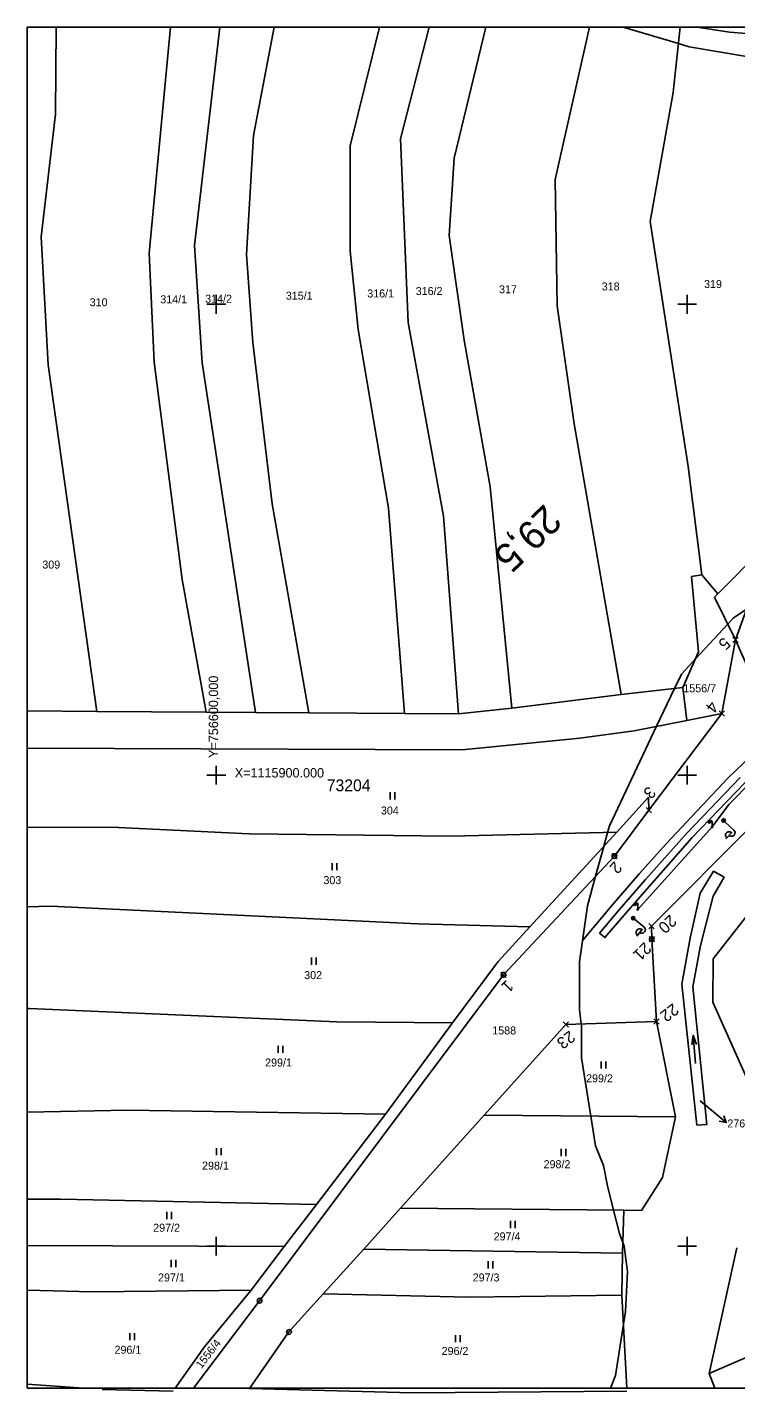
# Model space of a CAD drawing. Extents: x -756640 to -756220, y -1116031 to -1115741.
# Drawn here: x -756640.1 to -756489.7, y -1116031.1 to -1115741.2 of the extents above; entities that cross this region are included whole.
import ezdxf

# ---------------------------------------------------------------- set-up
doc = ezdxf.new("R2010")
doc.units = 0
for name, color, linetype in [('BPEJ', 7, 'Continuous'), ('GD_Demolice', 7, 'Continuous'), ('GD_Nový stav', 7, 'Continuous'), ('GD_Starý stav', 7, 'Continuous'), ('Groma (60)', 7, 'Continuous'), ('Katastr_HRANICE DRÁHY', 7, 'Continuous'), ('Katastr_Hranice parcel', 7, 'Continuous'), ('Katastr_Parcelní čísla', 7, 'Continuous'), ('Katastr_Značky kultur', 7, 'Continuous'), ('Vrstva 7', 7, 'Continuous'), ('čtvercová síť', 7, 'Continuous')]:
    doc.layers.add(name, color=color, linetype=linetype)

# ---------------------------------------------------------------- blocks, each defined once
blk = doc.blocks.new('POINT_DISPLAY')
for p, q in [((-0.56, -0.56), (0.56, 0.56)), ((-0.56, 0.56), (0.56, -0.56))]:
    blk.add_line(p, q)
blk = doc.blocks.new('C691')
at = {"layer": 'čtvercová síť'}
for p, q in [((-0.5, 0), (0.5, 0)), ((0, 0.5), (0, -0.5))]:
    blk.add_line(p, q, dxfattribs=at)

msp = doc.modelspace()

# ---------------------------------------------------------------- linework, layer by layer
at = {"layer": 'BPEJ'}
for points in [[(-756513.58, -1115741.18), (-756501.87, -1115744.61), (-756499.55, -1115745.29), (-756480.27, -1115748.57)], [(-756487.39, -1115864.74), (-756490.21, -1115866.65), (-756491.4, -1115867.93), (-756498.24, -1115875.3), (-756501.24, -1115878.53), (-756502.68, -1115881.57), (-756506.49, -1115889.6), (-756516.52, -1115910.78), (-756516.89, -1115912.13), (-756517.71, -1115915.1), (-756519.46, -1115921.46), (-756521.19, -1115927.75), (-756522.88, -1115939.63), (-756522.88, -1115949.82), (-756522.51, -1115952.82), (-756522.46, -1115953.21), (-756522.46, -1115960), (-756520.49, -1115972.39), (-756519.49, -1115978.67), (-756517.79, -1115982.91), (-756516.94, -1115987.16), (-756515.64, -1115992.37), (-756514.4, -1115997.34), (-756513.69, -1115999.21), (-756513.4, -1116000), (-756512.7, -1116005.4), (-756513.13, -1116013.89), (-756513.54, -1116016.57), (-756515.25, -1116027.47), (-756516.3, -1116030.18)]]:
    msp.add_lwpolyline(points, dxfattribs=at)
at = {"layer": 'Defpoints'}
for p, q in [((-756640.13, -1115741.18), (-756640.13, -1116030.18)), ((-756640.13, -1115741.18), (-756220.13, -1115741.18)), ((-756640.13, -1116030.18), (-756220.13, -1116030.18))]:
    msp.add_line(p, q, dxfattribs=at)
at = {"layer": 'GD_Demolice'}
for p, q in [((-756492.38, -1115909.27), (-756492.36, -1115909.98)), ((-756492.11, -1115909.29), (-756492.08, -1115909.95)), ((-756492, -1115909.88), (-756490.08, -1115911.67)), ((-756490.44, -1115912.06), (-756491.78, -1115913.48)), ((-756511.62, -1115929.99), (-756511.55, -1115930.7)), ((-756511.34, -1115929.99), (-756511.27, -1115930.65)), ((-756511.19, -1115930.57), (-756509.16, -1115932.23)), ((-756509.49, -1115932.64), (-756510.72, -1115934.15))]:
    msp.add_line(p, q, dxfattribs=at)
for centre in [(-756492.27, -1115909.62), (-756492.27, -1115909.62), (-756511.48, -1115930.34), (-756511.48, -1115930.34)]:
    msp.add_circle(centre, 0.375, dxfattribs=at)
for centre, start, end in [((-756491.11, -1115912.76), 46.1414, 227.5465), ((-756490.59, -1115912.22), 226.844, 46.844), ((-756510.11, -1115933.39), 50.1456, 231.5508), ((-756509.63, -1115932.81), 230.8482, 50.8482)]:
    msp.add_arc(centre, 0.75, start, end, dxfattribs=at)
at = {"layer": 'GD_Nový stav'}
for p, q in [((-756494.93, -1115909.87), (-756495.66, -1115909.87)), ((-756494.66, -1115911.11), (-756494.85, -1115910.93)), ((-756494.6, -1115911.04), (-756494.77, -1115910.86)), ((-756494.73, -1115910.85), (-756494.73, -1115909.87)), ((-756510.69, -1115927.37), (-756511.42, -1115927.37)), ((-756510.43, -1115928.62), (-756510.62, -1115928.43)), ((-756510.36, -1115928.54), (-756510.53, -1115928.37)), ((-756510.49, -1115928.36), (-756510.49, -1115927.37))]:
    msp.add_line(p, q, dxfattribs=at)
msp.add_lwpolyline([(-756510.49, -1115928.5), (-756494.73, -1115910.99), (-756491.19, -1115906.22), (-756486.18, -1115901.19), (-756481.67, -1115896.93), (-756478.14, -1115894.35), (-756473.87, -1115890.1), (-756473.74, -1115890.25)], dxfattribs=at)
for centre in [(-756494.73, -1115910.99), (-756494.73, -1115910.99), (-756510.49, -1115928.5), (-756510.49, -1115928.5)]:
    msp.add_circle(centre, 0.141, dxfattribs=at)
for centre, start, end in [((-756495.29, -1115909.87), 179.2811, 0.6862), ((-756495.01, -1115909.87), 359.9837, 179.9837), ((-756511.06, -1115927.38), 179.2811, 0.6862), ((-756510.77, -1115927.37), 359.9837, 179.9837)]:
    msp.add_arc(centre, 0.281, start, end, dxfattribs=at)
at = {"layer": 'GD_Starý stav'}
for p, q in [((-756480.69, -1115890.31), (-756491.34, -1115900.62)), ((-756491.34, -1115900.62), (-756504.48, -1115914.54)), ((-756488.75, -1115900.48), (-756500.01, -1115912.23)), ((-756499.99, -1115912.26), (-756488.72, -1115900.49)), ((-756500.01, -1115912.23), (-756508.86, -1115922.14)), ((-756508.86, -1115922.11), (-756499.99, -1115912.26)), ((-756504.48, -1115914.54), (-756510.1, -1115920.87)), ((-756510.1, -1115920.87), (-756515.92, -1115927.62)), ((-756508.86, -1115922.14), (-756514.44, -1115928.61)), ((-756514.43, -1115928.61), (-756508.86, -1115922.11)), ((-756515.92, -1115927.62), (-756522.16, -1115935.06)), ((-756514.44, -1115928.61), (-756518.65, -1115933.56)), ((-756518.61, -1115933.55), (-756514.43, -1115928.61)), ((-756518.65, -1115933.56), (-756518.61, -1115933.55))]:
    msp.add_line(p, q, dxfattribs=at)
msp.add_lwpolyline([(-756518.61, -1115933.55), (-756517.48, -1115934.49), (-756513.05, -1115929.32), (-756507.59, -1115923.05), (-756498.92, -1115913.24), (-756487.78, -1115901.64), (-756474.28, -1115888.97), (-756473.57, -1115888.27), (-756474.6, -1115887.22)], dxfattribs=at)
at = {"layer": 'Katastr_HRANICE DRÁHY'}
for points in [[(-756489.77, -1115871.26), (-756492.66, -1115886.9)], [(-756489.77, -1115871.26), (-756485.99, -1115879.76)], [(-756492.66, -1115886.9), (-756508.12, -1115907.44)], [(-756508.12, -1115907.44), (-756515.44, -1115917.16)], [(-756507.58, -1115932.04), (-756486.16, -1115910.54)], [(-756515.44, -1115917.16), (-756538.98, -1115942.37)], [(-756507.51, -1115934.79), (-756507.58, -1115932.04)], [(-756506.52, -1115952.32), (-756507.51, -1115934.79)], [(-756538.98, -1115942.37), (-756590.81, -1116011.58)], [(-756543.09, -1115972.17), (-756525.76, -1115952.92)], [(-756525.76, -1115952.92), (-756506.52, -1115952.32)], [(-756560.88, -1115991.93), (-756543.09, -1115972.17)], [(-756568.7, -1116000.61), (-756560.88, -1115991.93)], [(-756577.29, -1116010.16), (-756568.7, -1116000.61)], [(-756590.81, -1116011.58), (-756604.86, -1116030.18)], [(-756584.56, -1116018.23), (-756577.29, -1116010.16)], [(-756592.94, -1116030.24), (-756584.56, -1116018.23)]]:
    msp.add_lwpolyline(points, dxfattribs=at)
at = {"layer": 'Katastr_Hranice parcel'}
for points in [[(-756633.99, -1115741.18), (-756634.11, -1115759.63)], [(-756609.72, -1115741.18), (-756614.22, -1115789.17)], [(-756599.26, -1115741.18), (-756604.61, -1115787.49)], [(-756587.74, -1115741.18), (-756592.1, -1115764.13)], [(-756565.34, -1115741.18), (-756571.55, -1115766.34)], [(-756560.85, -1115764.89), (-756554.76, -1115741.18)], [(-756542.77, -1115741.18), (-756549.48, -1115768.99)], [(-756520.77, -1115741.18), (-756528.05, -1115773.51)], [(-756501.5, -1115741.18), (-756503, -1115755.02)], [(-756491, -1115742.18), (-756497.89, -1115741.18)], [(-756483.77, -1115742.78), (-756491, -1115742.18)], [(-756503, -1115755.02), (-756507.83, -1115782.44)], [(-756634.11, -1115759.63), (-756637.22, -1115785.67)], [(-756592.1, -1115764.13), (-756593.62, -1115789.44)], [(-756559.27, -1115803.88), (-756560.85, -1115764.89)], [(-756571.55, -1115766.34), (-756571.55, -1115788.68)], [(-756549.48, -1115768.99), (-756550.54, -1115785.37)], [(-756528.05, -1115773.51), (-756527.58, -1115800.34)], [(-756507.83, -1115782.44), (-756499.77, -1115834.45)], [(-756637.22, -1115785.67), (-756635.7, -1115812.82)], [(-756550.54, -1115785.37), (-756547.37, -1115807.58)], [(-756614.22, -1115789.17), (-756613.17, -1115812.3)], [(-756604.61, -1115787.49), (-756603.02, -1115812.4)], [(-756571.55, -1115788.68), (-756569.87, -1115805.33)], [(-756593.62, -1115789.44), (-756592.23, -1115808.14)], [(-756527.58, -1115800.34), (-756524.02, -1115825.38)], [(-756569.87, -1115805.33), (-756563.4, -1115843.32)], [(-756551.73, -1115844.98), (-756559.27, -1115803.88)], [(-756592.23, -1115808.14), (-756588.14, -1115842.37)], [(-756547.37, -1115807.58), (-756541.83, -1115838.76)], [(-756613.17, -1115812.3), (-756607.26, -1115858.45)], [(-756603.02, -1115812.4), (-756591.7, -1115886.68)], [(-756635.7, -1115812.82), (-756625.35, -1115886.44)], [(-756524.02, -1115825.38), (-756514.03, -1115882.86)], [(-756499.77, -1115834.45), (-756496.86, -1115857.44)], [(-756541.83, -1115838.76), (-756537.22, -1115885.77)], [(-756588.14, -1115842.37), (-756580.37, -1115886.76)], [(-756563.4, -1115843.32), (-756560.05, -1115886.9)], [(-756548.56, -1115886.98), (-756551.73, -1115844.98)], [(-756493.49, -1115861.47), (-756483.98, -1115851.89)], [(-756607.26, -1115858.45), (-756602.17, -1115886.61)], [(-756499.11, -1115857.77), (-756496.86, -1115857.44)], [(-756499.11, -1115857.77), (-756497.58, -1115873.81)], [(-756496.86, -1115857.44), (-756493.49, -1115861.47)], [(-756493.49, -1115861.47), (-756494.22, -1115862.2)], [(-756494.22, -1115862.2), (-756489.77, -1115871.26)], [(-756486.53, -1115862.38), (-756489.77, -1115871.26)], [(-756497.58, -1115873.81), (-756500.95, -1115881.37)], [(-756500.95, -1115881.37), (-756514.03, -1115882.86)], [(-756500.95, -1115881.37), (-756500.09, -1115888.35)], [(-756514.03, -1115882.86), (-756537.22, -1115885.77)], [(-756640.13, -1115886.33), (-756625.35, -1115886.44)], [(-756625.35, -1115886.44), (-756602.17, -1115886.61)], [(-756602.17, -1115886.61), (-756591.7, -1115886.68)], [(-756591.7, -1115886.68), (-756580.37, -1115886.76)], [(-756580.37, -1115886.76), (-756560.05, -1115886.9)], [(-756560.05, -1115886.9), (-756548.56, -1115886.98)], [(-756537.22, -1115885.77), (-756548.56, -1115886.98)], [(-756492.66, -1115886.9), (-756500.09, -1115888.35)], [(-756511.29, -1115890.54), (-756522.79, -1115892.12)], [(-756500.09, -1115888.35), (-756511.29, -1115890.54)], [(-756522.79, -1115892.12), (-756547.76, -1115894.63)], [(-756547.76, -1115894.63), (-756640.13, -1115894.26)], [(-756514.93, -1115912.08), (-756508.25, -1115904.68)], [(-756508.25, -1115904.68), (-756508.12, -1115907.44)], [(-756620.78, -1115911.11), (-756640.13, -1115911.02)], [(-756593.04, -1115912.43), (-756620.78, -1115911.11)], [(-756550.1, -1115912.96), (-756593.04, -1115912.43)], [(-756514.93, -1115912.08), (-756550.1, -1115912.96)], [(-756533.42, -1115932.16), (-756514.93, -1115912.08)], [(-756494.42, -1115920.34), (-756497.22, -1115925.01)], [(-756494.49, -1115925.71), (-756492.16, -1115921.66)], [(-756492.16, -1115921.66), (-756494.42, -1115920.34)], [(-756499.4, -1115934.6), (-756497.22, -1115925.01)], [(-756635.2, -1115927.8), (-756640.13, -1115927.95)], [(-756557.3, -1115931.53), (-756635.2, -1115927.8)], [(-756497.14, -1115936.16), (-756494.49, -1115925.71)], [(-756487.59, -1115930.19), (-756494.5, -1115938.97)], [(-756533.42, -1115932.16), (-756557.3, -1115931.53)], [(-756540.16, -1115939.57), (-756533.42, -1115932.16)], [(-756501.12, -1115944.34), (-756499.4, -1115934.6)], [(-756498.78, -1115944.97), (-756497.14, -1115936.16)], [(-756549.87, -1115952.58), (-756540.16, -1115939.57)], [(-756494.5, -1115938.97), (-756494.55, -1115948.16)], [(-756501.12, -1115944.34), (-756497.92, -1115974.28)], [(-756495.82, -1115974.2), (-756498.78, -1115944.97)], [(-756494.55, -1115948.16), (-756484.25, -1115971.34)], [(-756639.7, -1115949.54), (-756640.13, -1115949.54)], [(-756574.37, -1115952.38), (-756639.7, -1115949.54)], [(-756549.87, -1115952.58), (-756574.37, -1115952.38)], [(-756564.07, -1115971.94), (-756549.87, -1115952.58)], [(-756506.52, -1115952.32), (-756502.45, -1115972.57)], [(-756618.84, -1115971.15), (-756640.13, -1115971.58)], [(-756564.07, -1115971.94), (-756618.84, -1115971.15)], [(-756578.73, -1115991.17), (-756564.07, -1115971.94)], [(-756502.45, -1115972.57), (-756543.09, -1115972.17)], [(-756502.45, -1115972.57), (-756505.24, -1115985.42)], [(-756497.92, -1115974.28), (-756495.82, -1115974.2)], [(-756505.24, -1115985.42), (-756509.73, -1115992.43)], [(-756633.04, -1115990.05), (-756640.13, -1115990.03)], [(-756578.73, -1115991.17), (-756633.04, -1115990.05)], [(-756585.61, -1116000.09), (-756578.73, -1115991.17)], [(-756513.47, -1115992.39), (-756560.88, -1115991.93)], [(-756513.47, -1115992.39), (-756513.77, -1116001.5)], [(-756509.73, -1115992.43), (-756513.47, -1115992.39)], [(-756585.61, -1116000.09), (-756640.13, -1115999.84)], [(-756592.61, -1116009.35), (-756585.61, -1116000.09)], [(-756513.77, -1116001.5), (-756568.7, -1116000.61)], [(-756495.36, -1116027.02), (-756489.43, -1116000.35)], [(-756513.77, -1116001.5), (-756513.86, -1116010.4)], [(-756626.37, -1116009.68), (-756640.13, -1116009.34)], [(-756592.61, -1116009.35), (-756626.37, -1116009.68)], [(-756602.52, -1116021.37), (-756592.61, -1116009.35)], [(-756546.4, -1116010.82), (-756577.29, -1116010.16)], [(-756513.86, -1116010.4), (-756546.4, -1116010.82)], [(-756513.86, -1116010.4), (-756512.85, -1116030.18)], [(-756608.74, -1116030.18), (-756602.52, -1116021.37)], [(-756486.31, -1116023.12), (-756495.36, -1116027.02)], [(-756495.36, -1116027.02), (-756494.16, -1116030.18)], [(-756628.21, -1116030.18), (-756640.13, -1116029.29)], [(-756609.19, -1116030.82), (-756624.26, -1116030.47)], [(-756558.43, -1116031.12), (-756592.94, -1116030.24)], [(-756512.82, -1116030.77), (-756558.43, -1116031.12)]]:
    msp.add_lwpolyline(points, dxfattribs=at)
at = {"layer": 'Katastr_Parcelní čísla'}
for p, q in [((-756497.22, -1115969.13), (-756494.77, -1115971.18)), ((-756492.22, -1115972.34), (-756491.7, -1115973.75))]:
    msp.add_line(p, q, dxfattribs=at)
msp.add_lwpolyline([(-756494.77, -1115971.18), (-756491.7, -1115973.75), (-756493.18, -1115973.49)], dxfattribs=at)
at = {"layer": 'Katastr_Značky kultur'}
for p, q in [((-756563.07, -1115903.63), (-756563.07, -1115905.13)), ((-756562.07, -1115905.13), (-756562.07, -1115903.63)), ((-756575.41, -1115918.67), (-756575.41, -1115920.17)), ((-756574.41, -1115920.17), (-756574.41, -1115918.67)), ((-756515.49, -1115917.16), (-756515.39, -1115917.16)), ((-756507.56, -1115934.79), (-756507.46, -1115934.79)), ((-756579.77, -1115938.73), (-756579.77, -1115940.23)), ((-756578.77, -1115940.23), (-756578.77, -1115938.73)), ((-756539.03, -1115942.37), (-756538.93, -1115942.37)), ((-756586.85, -1115957.48), (-756586.85, -1115958.98)), ((-756585.85, -1115958.98), (-756585.85, -1115957.48)), ((-756498.22, -1115961.2), (-756498.72, -1115955.22)), ((-756518.29, -1115960.8), (-756518.29, -1115962.3)), ((-756517.29, -1115962.3), (-756517.29, -1115960.8)), ((-756599.98, -1115979.21), (-756599.98, -1115980.71)), ((-756598.98, -1115980.71), (-756598.98, -1115979.21)), ((-756526.79, -1115979.37), (-756526.79, -1115980.87)), ((-756525.79, -1115980.87), (-756525.79, -1115979.37)), ((-756610.48, -1115992.74), (-756610.48, -1115994.24)), ((-756609.48, -1115994.24), (-756609.48, -1115992.74)), ((-756537.55, -1115994.66), (-756537.55, -1115996.16)), ((-756536.55, -1115996.16), (-756536.55, -1115994.66)), ((-756609.57, -1116002.94), (-756609.57, -1116004.44)), ((-756608.57, -1116004.44), (-756608.57, -1116002.94)), ((-756542.28, -1116003.22), (-756542.28, -1116004.72)), ((-756541.28, -1116004.72), (-756541.28, -1116003.22)), ((-756590.86, -1116011.58), (-756590.76, -1116011.58)), ((-756584.61, -1116018.23), (-756584.51, -1116018.23)), ((-756618.38, -1116018.48), (-756618.38, -1116019.98)), ((-756617.38, -1116019.98), (-756617.38, -1116018.48)), ((-756549.22, -1116018.91), (-756549.22, -1116020.41)), ((-756548.22, -1116020.41), (-756548.22, -1116018.91))]:
    msp.add_line(p, q, dxfattribs=at)
msp.add_lwpolyline([(-756499.05, -1115957.25), (-756498.72, -1115955.22), (-756498.05, -1115957.17)], dxfattribs=at)
for centre in [(-756515.44, -1115917.16), (-756507.51, -1115934.79), (-756538.98, -1115942.37), (-756590.81, -1116011.58), (-756584.56, -1116018.23)]:
    msp.add_circle(centre, 0.499, dxfattribs=at)

# ---------------------------------------------------------------- block references
at = {"layer": 'Groma (60)', "rotation": 180}
for p in [(-756489.77, -1115871.26), (-756492.66, -1115886.9), (-756508.12, -1115907.44), (-756515.44, -1115917.16), (-756507.58, -1115932.04), (-756507.51, -1115934.79), (-756538.98, -1115942.37), (-756525.76, -1115952.92), (-756506.52, -1115952.32)]:
    msp.add_blockref('POINT_DISPLAY', p, dxfattribs=at)
at = {"layer": 'čtvercová síť', "xscale": 4, "yscale": 4}
for p in [(-756600, -1115800), (-756500, -1115800), (-756600, -1115900), (-756500, -1115900), (-756600, -1116000), (-756500, -1116000)]:
    msp.add_blockref('C691', p, dxfattribs=at)

# ---------------------------------------------------------------- texts
at = {"layer": 'BPEJ'}
msp.add_text('73204', height=2.5, dxfattribs=at).set_placement((-756576.54, -1115903.39))
at = {"layer": 'Groma (60)'}
for s, rotation, p in [('5', 223.2782, (-756492.24, -1115870.54)), ('4', 232.9958, (-756495.13, -1115884.05)), ('3', 226.833, (-756508.23, -1115902.18)), ('2', 229.0744, (-756515.46, -1115918.12)), ('20', 222.5601, (-756503.64, -1115929.47)), ('21', 224.6501, (-756509.08, -1115935.28)), ('1', 224.856, (-756538.34, -1115943.34)), ('22', 217.6049, (-756503.02, -1115948.32)), ('23', 216.9647, (-756524.96, -1115954.1))]:
    msp.add_text(s, height=2.5, rotation=rotation, dxfattribs=at).set_placement(p)
at = {"layer": 'Katastr_Parcelní čísla'}
for s, p in [('319', (-756496.42, -1115796.54)), ('314/1', (-756611.89, -1115799.79)), ('314/2', (-756602.36, -1115799.66)), ('315/1', (-756585.23, -1115799.01)), ('316/1', (-756567.94, -1115798.55)), ('316/2', (-756557.65, -1115798.03)), ('317', (-756539.95, -1115797.66)), ('318', (-756518.14, -1115797.05)), ('310', (-756626.88, -1115800.41)), ('309', (-756636.94, -1115856.12)), ('1556/7', (-756500.82, -1115882.39)), ('304', (-756565.04, -1115908.34)), ('303', (-756577.25, -1115923.12)), ('302', (-756581.33, -1115943.3)), ('1588', (-756541.39, -1115955.05)), ('299/1', (-756589.63, -1115961.85)), ('299/2', (-756521.47, -1115965.21)), ('276/3', (-756491.47, -1115974.8)), ('298/1', (-756603.02, -1115983.75)), ('298/2', (-756530.49, -1115983.45)), ('297/2', (-756613.4, -1115996.94)), ('297/4', (-756541.1, -1115998.78)), ('297/1', (-756612.37, -1116007.5)), ('297/3', (-756545.55, -1116007.5)), ('296/1', (-756621.61, -1116022.85)), ('296/2', (-756552.15, -1116023.11))]:
    msp.add_text(s, height=1.7, dxfattribs=at).set_placement(p)
msp.add_text('1556/4', height=1.7, rotation=52.3551, dxfattribs=at).set_placement((-756603.16, -1116026.13))
at = {"layer": 'Vrstva 7'}
msp.add_text('29,5', height=6, rotation=224.0682, dxfattribs=at).set_placement((-756530.3, -1115842.2))
at = {"layer": 'čtvercová síť'}
msp.add_text('Y=756600,000', height=2, rotation=90, dxfattribs=at).set_placement((-756599.61, -1115896.33))
msp.add_text('X=1115900.000', height=2, dxfattribs=at).set_placement((-756596.08, -1115900.48))

doc.saveas('drawing.dxf')
